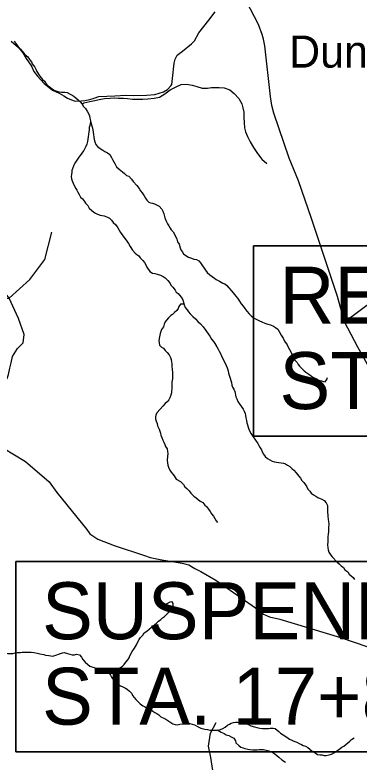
# Model space of a CAD drawing. Extents: x 0 to 69.5, y -4.5 to 22.
# Drawn here: x 2.351 to 3.197, y 18.449 to 20.286 of the extents above; entities that cross this region are included whole.
import ezdxf

# ---------------------------------------------------------------- set-up
doc = ezdxf.new("R2010")
doc.units = 0
for name, color, linetype in [('GM_X_County_Road', 7, 'Continuous'), ('GM_X_Minor_Lake', 7, 'Continuous'), ('GM_X_Minor_River', 7, 'Continuous'), ('GM_X_Township_Subdivision', 7, 'Continuous'), ('GM_X_Unincorporated_Text', 7, 'Continuous'), ('RD_P_Text', 7, 'Continuous'), ('SH_Masking', 7, 'Continuous')]:
    doc.layers.add(name, color=color, linetype=linetype)

msp = doc.modelspace()

# ---------------------------------------------------------------- linework, layer by layer
at = {"layer": 'GM_X_County_Road'}
for points in [[(3.2419, 19.3837), (3.194, 19.4694), (3.1615, 19.5318), (3.144, 19.5934), (3.08, 19.7852), (3.048, 19.8783), (3.0252, 19.9335), (2.9876, 20.0445), (2.9824, 20.0637), (2.9793, 20.0858), (2.9651, 20.2103), (2.9624, 20.2261), (2.9591, 20.2381), (2.9494, 20.2622), (2.9104, 20.3389)], [(2.5354, 20.0785), (2.5453, 20.0816), (2.5568, 20.0855), (2.5771, 20.0861), (2.5968, 20.087), (2.6233, 20.089), (2.6435, 20.0882), (2.6746, 20.0884), (2.6951, 20.0908), (2.7158, 20.0971), (2.7262, 20.1028), (2.7341, 20.1117), (2.7365, 20.1154), (2.738, 20.1294), (2.7426, 20.1673), (2.7452, 20.1775), (2.75, 20.1868), (2.7632, 20.1967), (2.7854, 20.215), (2.7924, 20.2224), (2.8032, 20.2418), (2.8273, 20.273), (2.8435, 20.2934)], [(2.3413, 20.2214), (2.3593, 20.2063), (2.3705, 20.1927), (2.3787, 20.1791), (2.3914, 20.1602), (2.3977, 20.1468), (2.4064, 20.1351), (2.423, 20.1174), (2.4436, 20.1011), (2.4593, 20.0933), (2.4712, 20.087), (2.4799, 20.0818), (2.49, 20.0773), (2.499, 20.0744), (2.5135, 20.0746), (2.5231, 20.0754), (2.5312, 20.0772), (2.5354, 20.0785)], [(3.1615, 19.5318), (3.309, 19.6416), (3.3205, 19.6464), (3.3314, 19.644), (3.3523, 19.6343), (3.3723, 19.6322), (3.3912, 19.6308), (3.413, 19.6354), (3.4316, 19.6411), (3.4543, 19.6464), (3.4685, 19.6532), (3.4832, 19.6621)], [(2.3226, 19.2206), (2.3768, 19.1884), (2.4348, 19.1381), (2.4542, 19.1116), (2.5273, 19.0205), (2.5349, 19.0104), (2.5546, 18.9972), (2.5951, 18.9816), (2.6698, 18.9569), (2.6833, 18.9516), (2.7119, 18.9461), (2.7624, 18.9381), (2.7782, 18.9339), (2.7928, 18.9251), (2.8077, 18.9174), (2.8446, 18.8965), (2.9426, 18.8282), (2.9622, 18.8128), (2.9768, 18.8059), (3.002, 18.8002), (3.1515, 18.7554), (3.2494, 18.722), (3.3671, 18.6835)]]:
    msp.add_lwpolyline(points, dxfattribs=at)
at = {"layer": 'GM_X_Minor_Lake'}
for points in [[(2.7314, 18.8419), (2.7187, 18.8345), (2.732, 18.8219)], [(2.732, 18.8219), (2.7351, 18.8216), (2.7402, 18.828), (2.7397, 18.839), (2.7371, 18.8429), (2.7314, 18.8419)]]:
    msp.add_lwpolyline(points, dxfattribs=at)
at = {"layer": 'GM_X_Minor_River'}
for points in [[(2.3492, 20.2221), (2.3525, 20.2167), (2.3577, 20.209), (2.3645, 20.202), (2.3686, 20.1966), (2.3756, 20.1885), (2.3824, 20.1827), (2.3865, 20.1761), (2.3917, 20.1707), (2.3935, 20.1657), (2.3994, 20.158), (2.4024, 20.1523), (2.4046, 20.1469), (2.412, 20.1353), (2.4187, 20.1276), (2.4232, 20.1234), (2.4261, 20.1187), (2.4329, 20.1114), (2.4385, 20.1075), (2.443, 20.1032), (2.449, 20.1005), (2.4562, 20.0977), (2.4608, 20.0968), (2.4653, 20.0964), (2.4737, 20.0959), (2.4794, 20.0954)], [(2.5154, 20.067), (2.5206, 20.07), (2.5347, 20.0731), (2.5473, 20.0755), (2.5576, 20.0779), (2.5709, 20.0802), (2.5854, 20.081), (2.5953, 20.0819), (2.6048, 20.0817), (2.618, 20.081), (2.6275, 20.0804), (2.6396, 20.079), (2.6521, 20.0787), (2.665, 20.0787), (2.678, 20.0796), (2.6928, 20.0811), (2.7062, 20.0842), (2.7196, 20.0923), (2.7324, 20.1018), (2.747, 20.1095), (2.76, 20.1149), (2.773, 20.1161), (2.7866, 20.1135), (2.7983, 20.1102), (2.8114, 20.106), (2.824, 20.1061), (2.8339, 20.1074), (2.8434, 20.1079), (2.8528, 20.1073), (2.8657, 20.1066), (2.8789, 20.1021), (2.8901, 20.0931), (2.9016, 20.0807), (2.9088, 20.0672), (2.9116, 20.0576), (2.9133, 20.0473), (2.9137, 20.034), (2.9142, 20.0218), (2.9154, 20.0085), (2.9178, 19.9989), (2.9224, 19.987), (2.929, 19.9743), (2.9374, 19.96), (2.9469, 19.9453), (2.9579, 19.931), (2.9706, 19.9204)], [(2.4794, 20.0954), (2.4958, 20.0867), (2.5017, 20.0816), (2.5062, 20.0773), (2.511, 20.0723), (2.5159, 20.0665), (2.5192, 20.0611), (2.5244, 20.056), (2.5284, 20.0495), (2.5314, 20.0441), (2.5339, 20.0376), (2.5353, 20.0322), (2.5367, 20.0258), (2.538, 20.0185), (2.5398, 20.0131), (2.5412, 20.0078), (2.5427, 20.0032), (2.5433, 19.9982), (2.5443, 19.9918), (2.545, 19.9853), (2.546, 19.9799), (2.547, 19.9742), (2.5495, 19.9677), (2.5536, 19.9627), (2.5603, 19.9576), (2.5667, 19.9537), (2.5723, 19.9505), (2.5783, 19.947), (2.584, 19.943), (2.5884, 19.9353), (2.5909, 19.9303), (2.5942, 19.9246), (2.5975, 19.9192), (2.6008, 19.9127), (2.6071, 19.9068), (2.6154, 19.9002), (2.6202, 19.8963), (2.6254, 19.8916), (2.6307, 19.8892), (2.6378, 19.8826), (2.6418, 19.8765), (2.6504, 19.8664), (2.6567, 19.859), (2.6592, 19.8537), (2.664, 19.849), (2.6688, 19.8413), (2.6721, 19.8352), (2.6754, 19.8305), (2.6799, 19.8255), (2.6844, 19.8243), (2.6893, 19.823), (2.6942, 19.8214), (2.6991, 19.8194), (2.7051, 19.8162), (2.7118, 19.8085), (2.7144, 19.8035), (2.7169, 19.797), (2.7197, 19.787), (2.7237, 19.7775), (2.7263, 19.7721), (2.7292, 19.7671), (2.7325, 19.7621), (2.7351, 19.7574), (2.7403, 19.7524), (2.745, 19.7436), (2.749, 19.7351), (2.7508, 19.7282), (2.7545, 19.7221), (2.757, 19.7136), (2.7591, 19.7087), (2.7617, 19.704), (2.7654, 19.6986), (2.771, 19.6944), (2.7774, 19.6908), (2.7853, 19.6876), (2.7909, 19.6856), (2.797, 19.6843), (2.803, 19.6812), (2.8071, 19.6761), (2.8118, 19.6688), (2.8159, 19.6634), (2.8192, 19.6588), (2.8233, 19.6526), (2.83, 19.6468), (2.8356, 19.6425), (2.8412, 19.6386), (2.8457, 19.6358), (2.8536, 19.6311), (2.8622, 19.6267), (2.8668, 19.6251), (2.872, 19.6208), (2.8768, 19.6154), (2.8824, 19.6084), (2.8872, 19.6026), (2.8938, 19.5945), (2.8979, 19.5895), (2.9031, 19.5825), (2.9075, 19.576), (2.912, 19.5702), (2.9164, 19.564), (2.9212, 19.5578)], [(2.537, 20.0238), (2.5358, 20.0185), (2.5349, 20.014), (2.5333, 20.0091), (2.5332, 20.0038), (2.5327, 19.9981), (2.5318, 19.9928), (2.5313, 19.9867), (2.5301, 19.9802), (2.5292, 19.9749), (2.5275, 19.9681), (2.5251, 19.9629), (2.5231, 19.9579), (2.52, 19.9531), (2.5173, 19.9486), (2.5141, 19.9437), (2.5083, 19.9362), (2.5012, 19.9261), (2.4985, 19.9215), (2.4957, 19.9163), (2.4933, 19.9102), (2.4909, 19.9038), (2.4905, 19.8993), (2.49, 19.894), (2.4895, 19.889), (2.4897, 19.8833), (2.4912, 19.878), (2.4937, 19.8722), (2.4962, 19.8668), (2.5003, 19.8595), (2.5032, 19.8549), (2.5058, 19.8503), (2.5087, 19.8449), (2.5124, 19.838), (2.5168, 19.8341), (2.522, 19.8275), (2.5246, 19.8229), (2.5302, 19.8171), (2.5335, 19.8109), (2.5398, 19.8055), (2.5446, 19.8012), (2.5491, 19.7984), (2.554, 19.7961), (2.5601, 19.794), (2.5657, 19.7928), (2.5703, 19.7923), (2.5782, 19.7891), (2.5831, 19.786), (2.5879, 19.7813), (2.5927, 19.7755), (2.599, 19.7697), (2.6042, 19.7627), (2.6071, 19.7566), (2.6108, 19.7512), (2.6149, 19.7454), (2.6189, 19.74), (2.6241, 19.7323), (2.6304, 19.7238), (2.6344, 19.7165), (2.6403, 19.708), (2.6462, 19.7003), (2.6507, 19.6971), (2.6552, 19.6936), (2.6589, 19.6886), (2.6656, 19.682), (2.6693, 19.6774), (2.6726, 19.6716), (2.6751, 19.6658), (2.6829, 19.655), (2.6893, 19.6515), (2.6949, 19.6499), (2.7002, 19.6486), (2.7089, 19.6461), (2.7153, 19.643), (2.7201, 19.6395), (2.7265, 19.6332), (2.7317, 19.6271), (2.7342, 19.6217), (2.739, 19.6163), (2.7446, 19.6093), (2.7475, 19.6047), (2.7524, 19.6012), (2.7598, 19.5919), (2.7635, 19.5853), (2.767, 19.5731), (2.7692, 19.5666), (2.774, 19.5608), (2.7777, 19.5562), (2.7818, 19.5515), (2.7881, 19.5445), (2.7948, 19.5387), (2.8007, 19.5325), (2.8074, 19.5263), (2.8134, 19.5189), (2.82, 19.51), (2.8259, 19.5019), (2.83, 19.4962), (2.834, 19.4888), (2.8388, 19.483), (2.8421, 19.478), (2.8469, 19.4699)], [(2.7665, 19.575), (2.7576, 19.5752), (2.7536, 19.5692), (2.752, 19.5643), (2.7489, 19.559), (2.7435, 19.5546), (2.7384, 19.5497), (2.7338, 19.5468), (2.7284, 19.5415), (2.7237, 19.5359), (2.7206, 19.5314), (2.7178, 19.5258), (2.7158, 19.5194), (2.7115, 19.5122), (2.7099, 19.5077), (2.7083, 19.5024), (2.7062, 19.4944), (2.7045, 19.4854), (2.7051, 19.4796), (2.7065, 19.4743), (2.7114, 19.4692), (2.7159, 19.4665), (2.7199, 19.4611), (2.7252, 19.456), (2.73, 19.4499), (2.7333, 19.4441), (2.7347, 19.4391), (2.7357, 19.433), (2.7367, 19.4284), (2.737, 19.4216), (2.7376, 19.4151), (2.7382, 19.406), (2.7379, 19.3911), (2.737, 19.3832), (2.7366, 19.3664), (2.7361, 19.3615), (2.736, 19.3565), (2.734, 19.3513), (2.7316, 19.3448), (2.7289, 19.3396), (2.7254, 19.3351), (2.7203, 19.3306), (2.7145, 19.3239), (2.7005, 19.3082), (2.6974, 19.3029), (2.6961, 19.2973), (2.6964, 19.2927), (2.6978, 19.2873), (2.7007, 19.2816), (2.7018, 19.2758), (2.7054, 19.2674), (2.7072, 19.2628), (2.7086, 19.2574), (2.7093, 19.2525), (2.7118, 19.2471), (2.7147, 19.2402), (2.7169, 19.2352), (2.7194, 19.2302), (2.7212, 19.2252), (2.7249, 19.2191), (2.7263, 19.213), (2.7266, 19.2076), (2.726, 19.2), (2.7255, 19.1917), (2.7261, 19.1848), (2.7267, 19.1791), (2.7285, 19.1738), (2.7318, 19.1668), (2.7351, 19.1618), (2.7388, 19.1572), (2.7425, 19.1526), (2.7477, 19.1448), (2.7578, 19.1386), (2.7652, 19.1312), (2.7689, 19.1254), (2.7738, 19.1219), (2.7794, 19.1161), (2.783, 19.1099), (2.7909, 19.1029), (2.7961, 19.0986), (2.8017, 19.0947), (2.8066, 19.0908), (2.8129, 19.0869), (2.8177, 19.0807), (2.8222, 19.0772), (2.827, 19.0706), (2.8307, 19.0648), (2.834, 19.0591), (2.8388, 19.0533), (2.8425, 19.0482), (2.8454, 19.0421), (2.8488, 19.0379)], [(2.9212, 19.5578), (2.9267, 19.5509), (2.9327, 19.5451), (2.9394, 19.5407), (2.9473, 19.5364), (2.9522, 19.534), (2.9582, 19.5312), (2.9654, 19.5284), (2.9729, 19.5256), (2.9793, 19.524), (2.9865, 19.5208), (2.9914, 19.5176), (2.997, 19.513), (3.0007, 19.5079), (3.0058, 19.4987), (3.0106, 19.491), (3.0135, 19.4841), (3.0205, 19.4752), (3.0226, 19.4695), (3.0263, 19.4637), (3.0289, 19.4579), (3.0318, 19.4518), (3.0362, 19.4437), (3.0394, 19.4368), (3.045, 19.4314), (3.0476, 19.4268), (3.0509, 19.4221), (3.0569, 19.4159), (3.0617, 19.4113), (3.0662, 19.4077), (3.0733, 19.4027), (3.0834, 19.3956), (3.0924, 19.3909), (3.0984, 19.3877), (3.1045, 19.3861), (3.1094, 19.3844), (3.1139, 19.3843), (3.1174, 19.3896), (3.1198, 19.3949)], [(2.8469, 19.4699), (2.8502, 19.4646), (2.8531, 19.4592), (2.8561, 19.4534), (2.859, 19.4469), (2.8619, 19.4415), (2.8648, 19.4357), (2.8681, 19.4296), (2.8706, 19.4238), (2.8728, 19.4185), (2.8749, 19.4108), (2.8763, 19.4055), (2.8774, 19.4005), (2.8799, 19.3928), (2.8821, 19.3875), (2.8831, 19.3821), (2.8845, 19.376), (2.8859, 19.3707), (2.8888, 19.3657), (2.8914, 19.3603), (2.8938, 19.3469), (2.8967, 19.3419), (2.8988, 19.3358), (2.904, 19.3285), (2.9084, 19.3219), (2.9117, 19.3165), (2.9147, 19.3119), (2.9168, 19.3061), (2.9175, 19.3008), (2.9189, 19.2951), (2.9203, 19.2886), (2.9209, 19.2832), (2.9223, 19.2783), (2.9245, 19.2725), (2.9259, 19.2672), (2.9288, 19.2618), (2.9318, 19.256), (2.9369, 19.2483), (2.948, 19.2321), (2.9509, 19.2271), (2.9538, 19.2217), (2.9568, 19.2167), (2.9586, 19.2117), (2.9619, 19.206), (2.9659, 19.2006), (2.9715, 19.1955), (2.9779, 19.1923), (2.9832, 19.1892), (2.9888, 19.1876), (2.9937, 19.1863), (2.9998, 19.1858), (3.0051, 19.1849), (3.0112, 19.1841), (3.0164, 19.1824), (3.0213, 19.1793), (3.0265, 19.1754), (3.0325, 19.1703), (3.037, 19.1664), (3.0422, 19.1602), (3.0488, 19.1517), (3.0533, 19.1467), (3.0566, 19.1417), (3.0611, 19.1367), (3.0655, 19.1305), (3.0684, 19.1259), (3.0714, 19.1201), (3.0758, 19.1151), (3.0795, 19.1104), (3.0847, 19.1058), (3.0904, 19.1026), (3.0956, 19.0998), (3.1013, 19.0974), (3.1058, 19.0958), (3.111, 19.0923), (3.1158, 19.0861), (3.1195, 19.08), (3.1197, 19.0731), (3.1196, 19.0666), (3.1201, 19.0526), (3.1207, 19.0461), (3.1221, 19.0396), (3.1228, 19.035), (3.1218, 19.0251), (3.1216, 19.0153), (3.1211, 19.0092), (3.1206, 19.0027), (3.1201, 18.9974), (3.12, 18.9898), (3.1194, 18.9837), (3.1204, 18.9754), (3.1211, 18.9708), (3.1229, 18.9647), (3.128, 18.9581), (3.131, 18.9535), (3.1432, 18.9407), (3.1477, 18.9364), (3.1529, 18.9317), (3.1585, 18.927), (3.1622, 18.922), (3.169, 18.9166), (3.173, 18.9112)], [(3.173, 18.9112), (3.1779, 18.9073), (3.1823, 18.9026), (3.1862, 18.8975)], [(2.4442, 18.709), (2.4676, 18.7176), (2.4722, 18.7183), (2.4797, 18.7162), (2.4861, 18.7146), (2.4918, 18.713), (2.4975, 18.7128), (2.5021, 18.7147), (2.5093, 18.713), (2.5148, 18.7068), (2.5181, 18.701), (2.5237, 18.6944), (2.5304, 18.689), (2.5353, 18.6851), (2.5398, 18.6835), (2.5454, 18.6811), (2.5522, 18.6783), (2.559, 18.6759), (2.5635, 18.6746), (2.5688, 18.6734), (2.5733, 18.6718), (2.5782, 18.6702), (2.5839, 18.67), (2.5896, 18.6714), (2.5958, 18.674), (2.6038, 18.6784), (2.6103, 18.6813), (2.615, 18.6846), (2.6192, 18.6891), (2.6239, 18.6943), (2.6282, 18.7), (2.6317, 18.7056), (2.6337, 18.7105), (2.6392, 18.7207), (2.6451, 18.7293), (2.6494, 18.7376), (2.6534, 18.7443), (2.6565, 18.75), (2.6593, 18.7552), (2.6655, 18.7612), (2.669, 18.7665), (2.6752, 18.7705), (2.6806, 18.7761), (2.6864, 18.7806), (2.691, 18.7839), (2.6987, 18.7902), (2.7042, 18.7958), (2.7095, 18.7995), (2.7138, 18.804), (2.7188, 18.8069), (2.7242, 18.8125), (2.7281, 18.817), (2.732, 18.8219)], [(2.3002, 18.7216), (2.3093, 18.7199), (2.315, 18.7187), (2.3199, 18.7175), (2.3252, 18.7166), (2.3332, 18.7161), (2.3389, 18.7156), (2.3454, 18.7163), (2.3515, 18.7173), (2.3572, 18.718), (2.3645, 18.7186), (2.369, 18.7193), (2.3904, 18.719), (2.3983, 18.7181), (2.4055, 18.7165), (2.4124, 18.7152), (2.4173, 18.714), (2.4218, 18.7131), (2.4264, 18.7119), (2.4344, 18.711), (2.4389, 18.7106), (2.4442, 18.709)], [(2.5806, 18.6701), (2.5857, 18.6628), (2.5886, 18.6574), (2.5923, 18.6524), (2.5983, 18.6469), (2.6057, 18.6399), (2.6106, 18.6364), (2.6162, 18.6336), (2.6226, 18.6308), (2.6271, 18.6285), (2.6327, 18.623), (2.6379, 18.6172), (2.6401, 18.6126), (2.6442, 18.6076), (2.6479, 18.603), (2.6534, 18.5975), (2.6586, 18.5921), (2.665, 18.5874), (2.6695, 18.5854), (2.6744, 18.5826), (2.6845, 18.5779), (2.6898, 18.5744), (2.6947, 18.5708), (2.6999, 18.5684), (2.7044, 18.5649), (2.71, 18.5603), (2.7171, 18.5571), (2.7216, 18.5543), (2.7291, 18.5492), (2.7393, 18.5433), (2.7445, 18.5413), (2.7495, 18.5408), (2.7563, 18.5418), (2.7628, 18.5432), (2.7685, 18.5442), (2.7738, 18.5441), (2.781, 18.5436), (2.7863, 18.542), (2.7927, 18.5403), (2.8017, 18.5356), (2.8081, 18.5324), (2.8179, 18.5299), (2.8244, 18.5287), (2.8304, 18.5274), (2.8422, 18.5272), (2.8475, 18.5278), (2.8559, 18.5292), (2.8624, 18.5317), (2.8674, 18.535), (2.8732, 18.5395), (2.8782, 18.5421), (2.8828, 18.5446), (2.8881, 18.546), (2.8934, 18.5467), (2.898, 18.547), (2.9082, 18.546), (2.9132, 18.5452), (2.9207, 18.5439), (2.9252, 18.5415), (2.9312, 18.5379), (2.9403, 18.5359), (2.9459, 18.5338), (2.9527, 18.5322), (2.9599, 18.5313), (2.9645, 18.5312), (2.9694, 18.5315), (2.974, 18.5318), (2.9786, 18.5324), (2.9854, 18.5323), (2.9907, 18.5314), (2.9997, 18.524), (3.0041, 18.5197), (3.0101, 18.5162), (3.0195, 18.5103), (3.0258, 18.5049), (3.0315, 18.5028), (3.0364, 18.5005), (3.0443, 18.4976), (3.0495, 18.4949), (3.0552, 18.4925), (3.0597, 18.4901), (3.0657, 18.4877), (3.071, 18.4846), (3.0758, 18.4803), (3.0829, 18.4752), (3.0889, 18.4713), (3.0949, 18.4677), (3.1002, 18.4669), (3.1059, 18.4664), (3.1112, 18.4655), (3.1165, 18.4654), (3.1238, 18.4668), (3.1291, 18.4686), (3.1364, 18.4726), (3.1472, 18.48), (3.1549, 18.4855), (3.1595, 18.4881), (3.1645, 18.4922), (3.1691, 18.4959), (3.1742, 18.5), (3.1788, 18.5041)], [(2.848, 18.5279), (2.8577, 18.5227), (2.8656, 18.5191), (2.8704, 18.5163), (2.8772, 18.5143), (2.8828, 18.5108), (2.8892, 18.5076), (2.8933, 18.5014), (2.8943, 18.4965), (2.9014, 18.4895), (2.9063, 18.486), (2.9119, 18.4843), (2.9164, 18.482), (2.9232, 18.4807), (2.9281, 18.4798), (2.9361, 18.4793), (2.9414, 18.4792), (2.9467, 18.4794), (2.9513, 18.4801), (2.9619, 18.4799), (2.9687, 18.4782), (2.9748, 18.4766), (2.9793, 18.4746), (2.9846, 18.4722), (2.9902, 18.4691), (2.995, 18.4655), (2.9999, 18.4609), (3.0074, 18.4546), (3.016, 18.4484)], [(3.1788, 18.5041), (3.1846, 18.5085)]]:
    msp.add_lwpolyline(points, dxfattribs=at)
at = {"layer": 'GM_X_Township_Subdivision'}
for points in [[(2.2376, 19.5862), (2.3368, 19.5895), (2.3878, 19.6353), (2.4245, 19.6849), (2.4413, 19.752)], [(2.2626, 19.3467), (2.2821, 19.3581), (2.3057, 19.3703), (2.3158, 19.376), (2.3242, 19.3834), (2.332, 19.3925), (2.3347, 19.4016), (2.3381, 19.4174), (2.3418, 19.4303), (2.3452, 19.4463), (2.3568, 19.4657), (2.371, 19.4799), (2.3736, 19.5005), (2.3594, 19.5399), (2.3368, 19.5895), (2.2601, 19.6888)], [(2.8512, 18.1737), (2.8536, 18.1924), (2.849, 18.2053), (2.8349, 18.2492), (2.8233, 18.2949), (2.8168, 18.342), (2.82, 18.3736), (2.831, 18.402), (2.8374, 18.4284), (2.8329, 18.46), (2.8265, 18.4884), (2.8316, 18.52), (2.8458, 18.5464)]]:
    msp.add_lwpolyline(points, dxfattribs=at)
at = {"layer": 'RD_P_Text'}
for points in [[(2.9371, 19.7183), (4.8665, 19.7183), (4.8665, 19.2501), (2.9371, 19.2501)], [(2.3533, 18.9424), (4.2827, 18.9424), (4.2827, 18.4742), (2.3533, 18.4742)]]:
    msp.add_lwpolyline(points, close=True, dxfattribs=at)
at = {"layer": 'SH_Masking'}
for points in [[(4.8665, 19.7183), (2.9371, 19.7183), (2.9371, 19.2501), (4.8665, 19.2501)], [(4.2827, 18.9424), (2.3533, 18.9424), (2.3533, 18.4742), (4.2827, 18.4742)]]:
    msp.add_lwpolyline(points, close=True, dxfattribs=at)

# ---------------------------------------------------------------- texts
at = {"layer": 'GM_X_Unincorporated_Text'}
msp.add_text('Dunlap', height=0.07898, rotation=0, dxfattribs=at).set_placement((3.025, 20.1565))
at = {"layer": 'RD_P_Text'}
for s, p in [('RESUME WALK', (3.0013, 19.5269)), ('STA. 18+38.04', (3.0013, 19.3169)), ('SUSPEND WALK', (2.4175, 18.751)), ('STA. 17+87.85', (2.4175, 18.541))]:
    msp.add_text(s, height=0.14, dxfattribs=at).set_placement(p)

doc.saveas('drawing.dxf')
